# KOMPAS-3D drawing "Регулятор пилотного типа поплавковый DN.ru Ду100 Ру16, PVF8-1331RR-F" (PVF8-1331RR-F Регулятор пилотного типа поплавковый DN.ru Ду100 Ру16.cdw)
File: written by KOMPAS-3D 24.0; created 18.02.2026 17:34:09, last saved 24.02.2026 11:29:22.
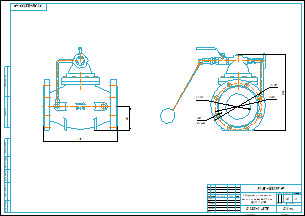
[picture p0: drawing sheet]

Document properties: art: D230-24375; Автор: R2D2; Форматы листов документа: A2; Полное имя файла: PVF8-1331RR-F Регулятор пилотного типа поплавковый DN.ru Ду100 Ру16.m3d; Масса: 18; Наименование: Регулятор пилотного типа поплавковый DN.ru Ду100 Ру16; Количество листов документа: 1; Примечание: D230-24375

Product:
- Part/product: Регулятор пилотного типа поплавковый DN.ru Ду100 Ру16  | designation PVF8-1331RR-F
    Масса: 18
    Раздел спецификации: Прочие изделия
    Примечание: D230-24375
    additional columns: D230-24375

Referenced files in E:\Работа\Зайцев\Для компаса\: чертеж DN.ru А3.cdt
Referenced files in E:\Работа\Зайцев\PVF8-1331RR-F Регулятор пилотного типа поплавковый DN.ru Ду15-300\DN100\: PVF8-1331RR-F Регулятор пилотного типа поплавковый DN.ru Ду100 Ру16.m3d
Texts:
  чертеж DN.ru А3.cdt
  Регулятор пилотного
  типа поплавковый DN.ru
  Ду100 Ру16
  PVF8-1331RR-F
  prop
  Регулятор пилотного типа поплавковый DN.ru Ду100 Ру16
  PVF8-1331RR-F Регулятор пилотного типа поплавковый DN.ru Ду100 Ру16
Dimensions and other numbers on the sheet: 1:2; 0; 1; 2; 18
